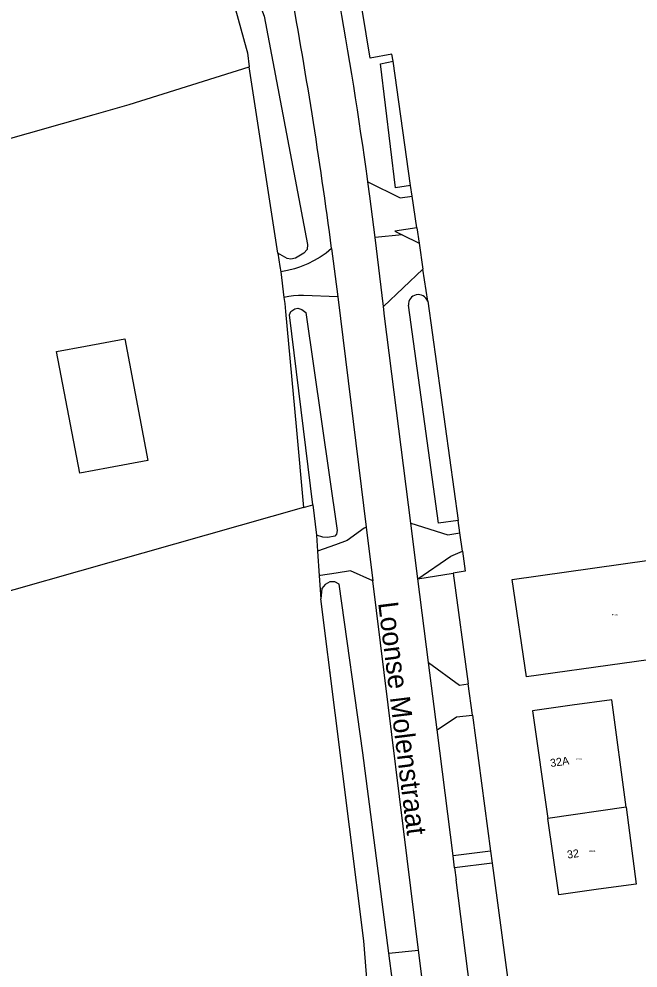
# Model space of a CAD drawing. Extents: x 134297 to 137000, y 403500 to 406000.
# Drawn here: x 134982 to 135059.3, y 403929.7 to 404048.3 of the extents above; entities that cross this region are included whole.
import ezdxf

# ---------------------------------------------------------------- set-up
doc = ezdxf.new("R2010")
doc.units = 0
for name, color, linetype in [('gg-anno-huisnummerreeks BGT', 7, 'Continuous'), ('gg-anno-openbare ruimte label', 7, 'Continuous'), ('gx-grn-maaiveld', 7, 'Continuous'), ('kenmerkpunt-x pandkandidaat', 7, 'Continuous')]:
    doc.layers.add(name, color=color, linetype=linetype)

msp = doc.modelspace()

# ---------------------------------------------------------------- linework, layer by layer
at = {"layer": 'gx-grn-maaiveld'}
for p, q in [((135014.3, 404019.03), (135010.69, 404042.31)), ((135030.84, 404027.48), (135028.67, 404043.03)), ((135031.04, 404026.15), (135030.84, 404027.48)), ((135031.63, 404022.19), (135031.04, 404026.15)), ((135031.63, 404022.19), (135031.92, 404020.29)), ((135029.83, 404021.33), (135026.42, 404020.98)), ((135027.47, 404012.38), (135026.42, 404020.98)), ((135029.83, 404021.33), (135031.92, 404020.29)), ((135031.92, 404020.29), (135032.4, 404017.04)), ((135021, 404019.6), (135021.76, 404013.56)), ((135014.64, 404016.72), (135015.05, 404013.49)), ((135027.47, 404012.38), (135032.4, 404017.04)), ((135033, 404013.04), (135032.4, 404017.04)), ((135021.76, 404013.56), (135025.32, 403984.82)), ((135033, 404013.04), (135036.8, 403985.65)), ((135017.49, 403987.27), (135018.64, 403987.6)), ((135018.64, 403987.6), (135019.11, 403983.8)), ((135037.01, 403984.08), (135036.8, 403985.65)), ((135025.32, 403984.82), (135026.15, 403978.09)), ((135031.77, 403978.34), (135030.89, 403985.29)), ((135019.11, 403983.8), (135019.24, 403981.79)), ((135037.33, 403981.79), (135037.01, 403984.08)), ((135019.24, 403981.79), (135019.45, 403978.73)), ((135019.45, 403978.73), (135019.65, 403975.84)), ((135031.77, 403978.34), (135036.19, 403979.07)), ((135033.1, 403967.88), (135031.77, 403978.34)), ((135036.19, 403979.07), (135038.06, 403965.22)), ((135031.86, 403931.96), (135026.15, 403978.09)), ((135034.17, 403959.46), (135033.1, 403967.88)), ((135038.58, 403961.32), (135038.06, 403965.22)), ((135038.58, 403961.32), (135040.85, 403944.32)), ((135036.17, 403943.72), (135034.17, 403959.46)), ((135057.78, 403949.8), (135048.02, 403948.4)), ((135040.85, 403944.32), (135036.17, 403943.72)), ((135040.85, 403944.32), (135041.05, 403942.83)), ((135036.36, 403942.24), (135036.17, 403943.72)), ((135041.05, 403942.83), (135036.36, 403942.24)), ((135041.05, 403942.83), (135041.26, 403941.26)), ((135036.36, 403942.24), (135036.54, 403940.75)), ((135038.88, 403922.37), (135036.54, 403940.75)), ((135041.26, 403941.26), (135044.04, 403920.45)), ((135028.14, 403931.59), (135031.86, 403931.96)), ((135033.76, 403916.63), (135031.86, 403931.96))]:
    msp.add_line(p, q, dxfattribs=at)
for points in [[(135028.67, 404043.03), (135028.54, 404043.92), (135025.8, 404043.4), (135023.3, 404058.65), (135023.29, 404058.69)], [(135007.91, 404053.82), (135008.1, 404054.32), (135008.27, 404054.61), (135008.67, 404054.9), (135009.39, 404055.02), (135010.27, 404054.72), (135012.59, 404048.64), (135018, 404020.12), (135017.96, 404019.48), (135017.55, 404019.02), (135016.49, 404018.4), (135015.9, 404018.3), (135015.44, 404018.37), (135014.3, 404019.03)], [(135007.91, 404053.82), (135007.98, 404053.16), (135010.32, 404044.65), (135010.49, 404044.05), (135010.69, 404042.31)], [(135017.49, 403987.27), (134953.29, 403969.03), (134938.43, 404021.32), (134991.36, 404036.36), (134995.7, 404037.6), (135010.69, 404042.31)], [(135030.84, 404027.48), (135028.99, 404027.22), (135027.12, 404042.68), (135028.67, 404043.03)], [(135025.53, 404027.94), (135025.43, 404028.67), (135025.3, 404029.57)], [(135026.42, 404020.98), (135025.77, 404026.15), (135025.53, 404027.94)], [(135025.53, 404027.94), (135029.57, 404025.93), (135031.04, 404026.15)], [(135031.63, 404022.19), (135028.91, 404021.79), (135029.83, 404021.33)], [(135014.3, 404019.03), (135014.55, 404017.39), (135014.64, 404016.72)], [(135021, 404019.6), (135020.32, 404019.05), (135019.59, 404018.55), (135018.83, 404018.1), (135018.03, 404017.7), (135017.2, 404017.36), (135017, 404017.3), (135016.36, 404017.08), (135015.5, 404016.87), (135014.64, 404016.72)], [(135021.76, 404013.56), (135017.49, 404013.73), (135016.87, 404013.73), (135016.26, 404013.69), (135015.65, 404013.61), (135015.05, 404013.49)], [(135015.05, 404013.49), (135015.15, 404012.75), (135015.24, 404011.75), (135016.56, 403997.36), (135017.49, 403987.27)], [(135018.64, 403987.6), (135015.73, 404011.35), (135015.89, 404011.75), (135016.39, 404012.1), (135016.8, 404012.16), (135017.26, 404011.99), (135017.76, 404011.61), (135021.71, 403984.38), (135021.62, 403983.94), (135021.42, 403983.69), (135020.52, 403983.51), (135019.91, 403983.55), (135019.11, 403983.8)], [(135030.89, 403985.29), (135027.6, 404011.17), (135027.47, 404012.38)], [(135036.8, 403985.65), (135034.33, 403985.31), (135030.59, 404012.54)], [(134995.16, 404008.35), (134998.03, 403993.13), (134993.12, 403992.21), (134989.54, 403991.53), (134986.66, 404006.75), (134990.25, 404007.42), (134995.16, 404008.35)], [(135025.32, 403984.82), (135025.08, 403984.66), (135022.93, 403983.13), (135021.47, 403982.6), (135019.24, 403981.79)], [(135030.89, 403985.29), (135035.52, 403983.83), (135037.01, 403984.08)], [(135031.77, 403978.34), (135035.9, 403981.17), (135037.33, 403981.79)], [(135037.33, 403981.79), (135037.67, 403979.32), (135036.19, 403979.07)], [(135067.45, 403981.63), (135069.22, 403969.43), (135045.32, 403966.08), (135043.54, 403978.28), (135067.45, 403981.63)], [(135026.15, 403978.09), (135023.36, 403979.33), (135021.55, 403979.06), (135019.62, 403978.76), (135019.45, 403978.73)], [(135028.14, 403931.59), (135024.89, 403956.59), (135021.96, 403977.69), (135021.4, 403977.97), (135020.79, 403977.96), (135020.21, 403977.63), (135019.79, 403977.14), (135019.65, 403975.84)], [(135025.95, 403921.55), (135025.02, 403933.1), (135019.65, 403975.84)], [(135033.1, 403967.88), (135036.99, 403965.04), (135038.06, 403965.22)], [(135057.78, 403949.8), (135056, 403963.24), (135051.03, 403962.58), (135046.08, 403961.87), (135048.02, 403948.4)], [(135034.17, 403959.46), (135036.61, 403961.1), (135038.58, 403961.32)], [(135057.78, 403949.8), (135059.05, 403940.2), (135054.34, 403939.58), (135049.39, 403938.87), (135048.02, 403948.4)], [(135029.37, 403920.46), (135029.05, 403924.58), (135028.14, 403931.59)]]:
    msp.add_lwpolyline(points, dxfattribs=at)
for centre, radius, start, end in [((134401.98, 403938.5), 624.31, 7.46467, 10.58418), ((134424.2, 403945.09), 607.01, 8.0004, 10.25556), ((135031.83, 404012.61), 1.25, 19.9647, 183.4486)]:
    msp.add_arc(centre, radius, start, end, dxfattribs=at)

# ---------------------------------------------------------------- texts
at = {"layer": 'gg-anno-huisnummerreeks BGT'}
for s, p in [('32A', (135048.37, 403954.82)), ('32', (135050.48, 403943.38))]:
    msp.add_text(s, height=1, rotation=8.2, dxfattribs=at).set_placement(p)
at = {"layer": 'gg-anno-openbare ruimte label'}
msp.add_text('Loonse Molenstraat', height=2.5, rotation=277.1, dxfattribs=at).set_placement((135026.8, 403975.34))
at = {"layer": 'kenmerkpunt-x pandkandidaat'}
for p in [(135056.01, 403973.75), (135051.56, 403955.73), (135053.16, 403944.23)]:
    msp.add_text('PNDK', height=0.2, dxfattribs=at).set_placement(p)

doc.saveas('drawing.dxf')
